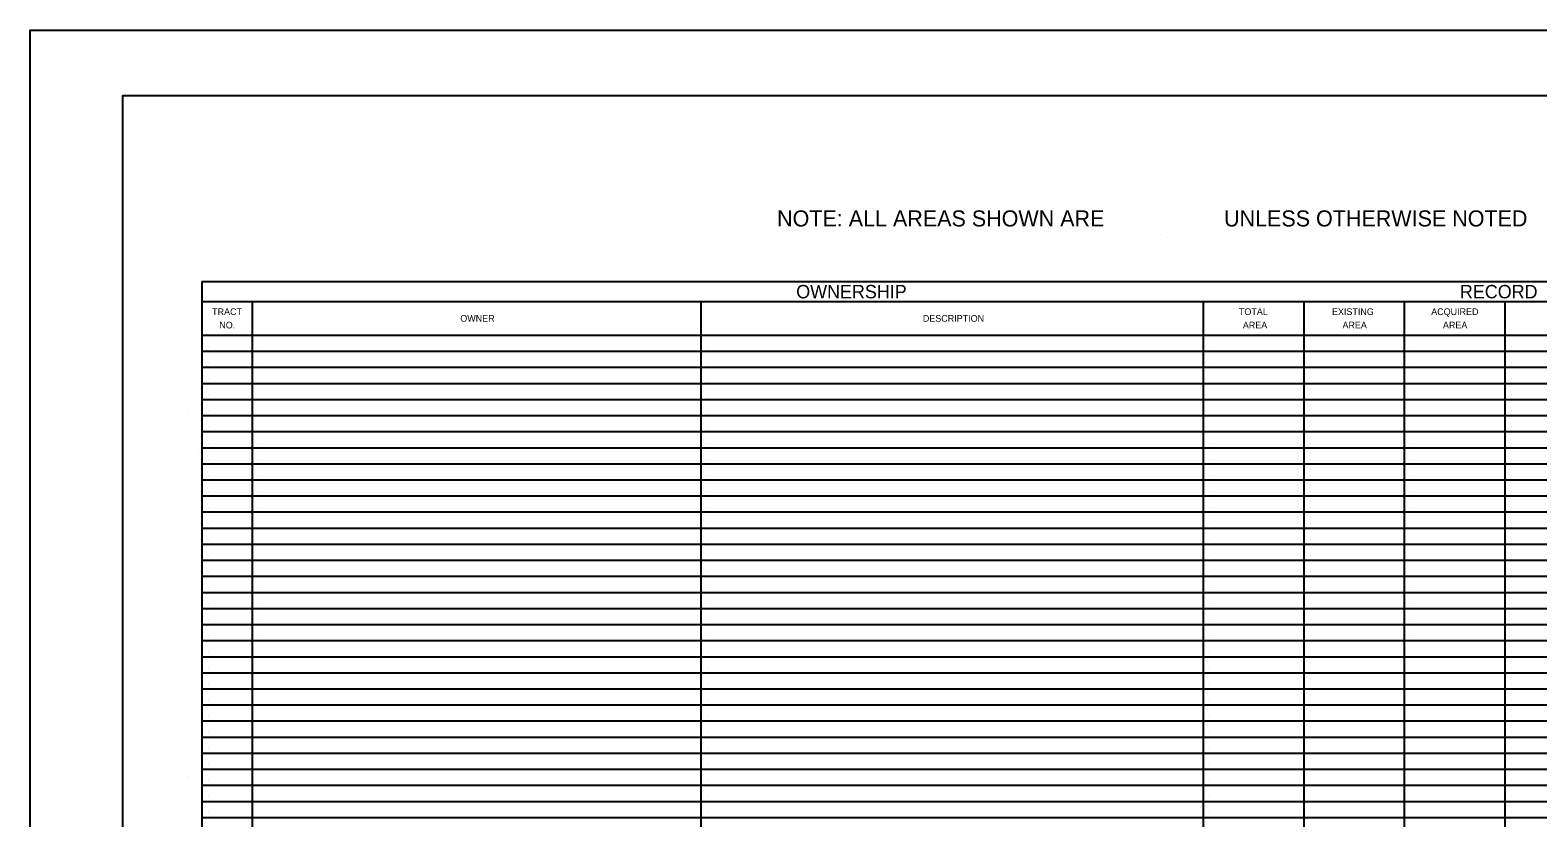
# Model space of a CAD drawing. Extents: x 0 to 3.48, y 0 to 2.25.
# Drawn here: x 0 to 1.913, y 1 to 2 of the extents above; entities that cross this region are included whole.
import ezdxf

# ---------------------------------------------------------------- set-up
doc = ezdxf.new("R2010")
doc.units = 0
for name, color, linetype in [('Border Active Points', 7, 'Continuous'), ('Border Line', 7, 'Continuous'), ('Border Organizer Shape', 7, 'Continuous')]:
    doc.layers.add(name, color=color, linetype=linetype)

msp = doc.modelspace()

# ---------------------------------------------------------------- linework, layer by layer
at = {"layer": 'Border Active Points'}
for p, q in [((1.4437, 1.7373), (1.4437, 1.7373)), ((0.2262, 1.5985), (0.2262, 1.5985)), ((0.29, 1.5985), (0.29, 1.5985)), ((0.8595, 1.5985), (0.8595, 1.5985)), ((1.497, 1.5985), (1.497, 1.5985)), ((1.6245, 1.5985), (1.6245, 1.5985)), ((1.752, 1.5985), (1.752, 1.5985)), ((1.8795, 1.5985), (1.8795, 1.5985)), ((0.2262, 1.5781), (0.2262, 1.5781)), ((0.29, 1.5781), (0.29, 1.5781)), ((0.8595, 1.5781), (0.8595, 1.5781)), ((1.497, 1.5781), (1.497, 1.5781)), ((1.6245, 1.5781), (1.6245, 1.5781)), ((1.752, 1.5781), (1.752, 1.5781)), ((1.8795, 1.5781), (1.8795, 1.5781)), ((0.2262, 1.5577), (0.2262, 1.5577)), ((0.29, 1.5577), (0.29, 1.5577)), ((0.8595, 1.5577), (0.8595, 1.5577)), ((1.497, 1.5577), (1.497, 1.5577)), ((1.6245, 1.5577), (1.6245, 1.5577)), ((1.752, 1.5577), (1.752, 1.5577)), ((1.8795, 1.5577), (1.8795, 1.5577)), ((0.2262, 1.5373), (0.2262, 1.5373)), ((0.29, 1.5373), (0.29, 1.5373)), ((0.8595, 1.5373), (0.8595, 1.5373)), ((1.497, 1.5373), (1.497, 1.5373)), ((1.6245, 1.5373), (1.6245, 1.5373)), ((1.752, 1.5373), (1.752, 1.5373)), ((1.8795, 1.5373), (1.8795, 1.5373)), ((0.2002, 1.5179), (0.2002, 1.5179)), ((0.2262, 1.5169), (0.2262, 1.5169)), ((0.29, 1.5169), (0.29, 1.5169)), ((0.8595, 1.5169), (0.8595, 1.5169)), ((1.497, 1.5169), (1.497, 1.5169)), ((1.6245, 1.5169), (1.6245, 1.5169)), ((1.752, 1.5169), (1.752, 1.5169)), ((1.8795, 1.5169), (1.8795, 1.5169)), ((0.2262, 1.4965), (0.2262, 1.4965)), ((0.29, 1.4965), (0.29, 1.4965)), ((0.8595, 1.4965), (0.8595, 1.4965)), ((1.497, 1.4965), (1.497, 1.4965)), ((1.6245, 1.4965), (1.6245, 1.4965)), ((1.752, 1.4965), (1.752, 1.4965)), ((1.8795, 1.4965), (1.8795, 1.4965)), ((0.2262, 1.4761), (0.2262, 1.4761)), ((0.29, 1.4761), (0.29, 1.4761)), ((0.8595, 1.4761), (0.8595, 1.4761)), ((1.497, 1.4761), (1.497, 1.4761)), ((1.6245, 1.4761), (1.6245, 1.4761)), ((1.752, 1.4761), (1.752, 1.4761)), ((1.8795, 1.4761), (1.8795, 1.4761)), ((0.2142, 1.4665), (0.2142, 1.4665)), ((0.2262, 1.4557), (0.2262, 1.4557)), ((0.29, 1.4557), (0.29, 1.4557)), ((0.8595, 1.4557), (0.8595, 1.4557)), ((1.497, 1.4557), (1.497, 1.4557)), ((1.6245, 1.4557), (1.6245, 1.4557)), ((1.752, 1.4557), (1.752, 1.4557)), ((1.8795, 1.4557), (1.8795, 1.4557)), ((0.2262, 1.4353), (0.2262, 1.4353)), ((0.29, 1.4353), (0.29, 1.4353)), ((0.8595, 1.4353), (0.8595, 1.4353)), ((1.497, 1.4353), (1.497, 1.4353)), ((1.6245, 1.4353), (1.6245, 1.4353)), ((1.752, 1.4353), (1.752, 1.4353)), ((1.8795, 1.4353), (1.8795, 1.4353)), ((0.2262, 1.4149), (0.2262, 1.4149)), ((0.29, 1.4149), (0.29, 1.4149)), ((0.8595, 1.4149), (0.8595, 1.4149)), ((1.497, 1.4149), (1.497, 1.4149)), ((1.6245, 1.4149), (1.6245, 1.4149)), ((1.752, 1.4149), (1.752, 1.4149)), ((1.8795, 1.4149), (1.8795, 1.4149)), ((0.2262, 1.3945), (0.2262, 1.3945)), ((0.29, 1.3945), (0.29, 1.3945)), ((0.8595, 1.3945), (0.8595, 1.3945)), ((1.497, 1.3945), (1.497, 1.3945)), ((1.6245, 1.3945), (1.6245, 1.3945)), ((1.752, 1.3945), (1.752, 1.3945)), ((1.8795, 1.3945), (1.8795, 1.3945)), ((0.2262, 1.3741), (0.2262, 1.3741)), ((0.29, 1.3741), (0.29, 1.3741)), ((0.8595, 1.3741), (0.8595, 1.3741)), ((1.497, 1.3741), (1.497, 1.3741)), ((1.6245, 1.3741), (1.6245, 1.3741)), ((1.752, 1.3741), (1.752, 1.3741)), ((1.8795, 1.3741), (1.8795, 1.3741)), ((0.2262, 1.3537), (0.2262, 1.3537)), ((0.29, 1.3537), (0.29, 1.3537)), ((0.8595, 1.3537), (0.8595, 1.3537)), ((1.497, 1.3537), (1.497, 1.3537)), ((1.6245, 1.3537), (1.6245, 1.3537)), ((1.752, 1.3537), (1.752, 1.3537)), ((1.8795, 1.3537), (1.8795, 1.3537)), ((0.2262, 1.3333), (0.2262, 1.3333)), ((0.29, 1.3333), (0.29, 1.3333)), ((0.8595, 1.3333), (0.8595, 1.3333)), ((1.497, 1.3333), (1.497, 1.3333)), ((1.6245, 1.3333), (1.6245, 1.3333)), ((1.752, 1.3333), (1.752, 1.3333)), ((1.8795, 1.3333), (1.8795, 1.3333)), ((0.2262, 1.3129), (0.2262, 1.3129)), ((0.29, 1.3129), (0.29, 1.3129)), ((0.8595, 1.3129), (0.8595, 1.3129)), ((1.497, 1.3129), (1.497, 1.3129)), ((1.6245, 1.3129), (1.6245, 1.3129)), ((1.752, 1.3129), (1.752, 1.3129)), ((1.8795, 1.3129), (1.8795, 1.3129)), ((0.2262, 1.2925), (0.2262, 1.2925)), ((0.29, 1.2925), (0.29, 1.2925)), ((0.8595, 1.2925), (0.8595, 1.2925)), ((1.497, 1.2925), (1.497, 1.2925)), ((1.6245, 1.2925), (1.6245, 1.2925)), ((1.752, 1.2925), (1.752, 1.2925)), ((1.8795, 1.2925), (1.8795, 1.2925)), ((0.2262, 1.2721), (0.2262, 1.2721)), ((0.29, 1.2721), (0.29, 1.2721)), ((0.8595, 1.2721), (0.8595, 1.2721)), ((1.497, 1.2721), (1.497, 1.2721)), ((1.6245, 1.2721), (1.6245, 1.2721)), ((1.752, 1.2721), (1.752, 1.2721)), ((1.8795, 1.2721), (1.8795, 1.2721)), ((0.2262, 1.2517), (0.2262, 1.2517)), ((0.29, 1.2517), (0.29, 1.2517)), ((0.8595, 1.2517), (0.8595, 1.2517)), ((1.497, 1.2517), (1.497, 1.2517)), ((1.6245, 1.2517), (1.6245, 1.2517)), ((1.752, 1.2517), (1.752, 1.2517)), ((1.8795, 1.2517), (1.8795, 1.2517)), ((0.2262, 1.2313), (0.2262, 1.2313)), ((0.29, 1.2313), (0.29, 1.2313)), ((0.8595, 1.2313), (0.8595, 1.2313)), ((1.497, 1.2313), (1.497, 1.2313)), ((1.6245, 1.2313), (1.6245, 1.2313)), ((1.752, 1.2313), (1.752, 1.2313)), ((1.8795, 1.2313), (1.8795, 1.2313)), ((0.2262, 1.2109), (0.2262, 1.2109)), ((0.29, 1.2109), (0.29, 1.2109)), ((0.8595, 1.2109), (0.8595, 1.2109)), ((1.497, 1.2109), (1.497, 1.2109)), ((1.6245, 1.2109), (1.6245, 1.2109)), ((1.752, 1.2109), (1.752, 1.2109)), ((1.8795, 1.2109), (1.8795, 1.2109)), ((0.2262, 1.1905), (0.2262, 1.1905)), ((0.29, 1.1905), (0.29, 1.1905)), ((0.8595, 1.1905), (0.8595, 1.1905)), ((1.497, 1.1905), (1.497, 1.1905)), ((1.6245, 1.1905), (1.6245, 1.1905)), ((1.752, 1.1905), (1.752, 1.1905)), ((1.8795, 1.1905), (1.8795, 1.1905)), ((0.2262, 1.1701), (0.2262, 1.1701)), ((0.29, 1.1701), (0.29, 1.1701)), ((0.8595, 1.1701), (0.8595, 1.1701)), ((1.497, 1.1701), (1.497, 1.1701)), ((1.6245, 1.1701), (1.6245, 1.1701)), ((1.752, 1.1701), (1.752, 1.1701)), ((1.8795, 1.1701), (1.8795, 1.1701)), ((0.2262, 1.1497), (0.2262, 1.1497)), ((0.29, 1.1497), (0.29, 1.1497)), ((0.8595, 1.1497), (0.8595, 1.1497)), ((1.497, 1.1497), (1.497, 1.1497)), ((1.6245, 1.1497), (1.6245, 1.1497)), ((1.752, 1.1497), (1.752, 1.1497)), ((1.8795, 1.1497), (1.8795, 1.1497)), ((0.2262, 1.1293), (0.2262, 1.1293)), ((0.29, 1.1293), (0.29, 1.1293)), ((0.8595, 1.1293), (0.8595, 1.1293)), ((1.497, 1.1293), (1.497, 1.1293)), ((1.6245, 1.1293), (1.6245, 1.1293)), ((1.752, 1.1293), (1.752, 1.1293)), ((1.8795, 1.1293), (1.8795, 1.1293)), ((0.2262, 1.1089), (0.2262, 1.1089)), ((0.29, 1.1089), (0.29, 1.1089)), ((0.8595, 1.1089), (0.8595, 1.1089)), ((1.497, 1.1089), (1.497, 1.1089)), ((1.6245, 1.1089), (1.6245, 1.1089)), ((1.752, 1.1089), (1.752, 1.1089)), ((1.8795, 1.1089), (1.8795, 1.1089)), ((0.2262, 1.0885), (0.2262, 1.0885)), ((0.29, 1.0885), (0.29, 1.0885)), ((0.8595, 1.0885), (0.8595, 1.0885)), ((1.497, 1.0885), (1.497, 1.0885)), ((1.6245, 1.0885), (1.6245, 1.0885)), ((1.752, 1.0885), (1.752, 1.0885)), ((1.8795, 1.0885), (1.8795, 1.0885)), ((0.2262, 1.0681), (0.2262, 1.0681)), ((0.29, 1.0681), (0.29, 1.0681)), ((0.8595, 1.0681), (0.8595, 1.0681)), ((1.497, 1.0681), (1.497, 1.0681)), ((1.6245, 1.0681), (1.6245, 1.0681)), ((1.752, 1.0681), (1.752, 1.0681)), ((1.8795, 1.0681), (1.8795, 1.0681)), ((0.2002, 1.0514), (0.2002, 1.0514)), ((0.2262, 1.0477), (0.2262, 1.0477)), ((0.29, 1.0477), (0.29, 1.0477)), ((0.8595, 1.0477), (0.8595, 1.0477)), ((1.497, 1.0477), (1.497, 1.0477)), ((1.6245, 1.0477), (1.6245, 1.0477)), ((1.752, 1.0477), (1.752, 1.0477)), ((1.8795, 1.0477), (1.8795, 1.0477)), ((0.2262, 1.0273), (0.2262, 1.0273)), ((0.29, 1.0273), (0.29, 1.0273)), ((0.8595, 1.0273), (0.8595, 1.0273)), ((1.497, 1.0273), (1.497, 1.0273)), ((1.6245, 1.0273), (1.6245, 1.0273)), ((1.752, 1.0273), (1.752, 1.0273)), ((1.8795, 1.0273), (1.8795, 1.0273)), ((0.2262, 1.0069), (0.2262, 1.0069)), ((0.29, 1.0069), (0.29, 1.0069)), ((0.8595, 1.0069), (0.8595, 1.0069)), ((1.497, 1.0069), (1.497, 1.0069)), ((1.6245, 1.0069), (1.6245, 1.0069)), ((1.752, 1.0069), (1.752, 1.0069)), ((1.8795, 1.0069), (1.8795, 1.0069))]:
    msp.add_line(p, q, dxfattribs=at)
at = {"layer": 'Border Line'}
for p, q in [((0.2177, 1.681), (2.6827, 1.681)), ((0.2177, 1.681), (0.2177, 0.185)), ((0.2177, 1.6555), (2.6827, 1.6555)), ((0.2815, 1.6555), (0.2815, 0.185)), ((0.851, 1.6555), (0.851, 0.1893)), ((1.4885, 1.6555), (1.4885, 0.185)), ((1.616, 1.6555), (1.616, 0.185)), ((1.7435, 1.6555), (1.7435, 0.185)), ((1.871, 1.6555), (1.871, 0.185)), ((0.2177, 1.613), (2.6827, 1.613)), ((0.2177, 1.5926), (2.6827, 1.5926)), ((0.2177, 1.5722), (2.6827, 1.5722)), ((0.2177, 1.5518), (2.6827, 1.5518)), ((0.2177, 1.5314), (2.6827, 1.5314)), ((0.2177, 1.511), (2.6827, 1.511)), ((0.2177, 1.4906), (2.6827, 1.4906)), ((0.2177, 1.4702), (2.6827, 1.4702)), ((0.2177, 1.4498), (2.6827, 1.4498)), ((0.2177, 1.4294), (2.6827, 1.4294)), ((0.2177, 1.409), (2.6827, 1.409)), ((0.2177, 1.3886), (2.6827, 1.3886)), ((0.2177, 1.3682), (2.6827, 1.3682)), ((0.2177, 1.3478), (2.6827, 1.3478)), ((0.2177, 1.3274), (2.6827, 1.3274)), ((0.2177, 1.307), (2.6827, 1.307)), ((0.2177, 1.2866), (2.6827, 1.2866)), ((0.2177, 1.2662), (2.6827, 1.2662)), ((0.2177, 1.2458), (2.6827, 1.2458)), ((0.2177, 1.2254), (2.6827, 1.2254)), ((0.2177, 1.205), (2.6827, 1.205)), ((0.2177, 1.1846), (2.6827, 1.1846)), ((0.2177, 1.1642), (2.6827, 1.1642)), ((0.2177, 1.1438), (2.6827, 1.1438)), ((0.2177, 1.1234), (2.6827, 1.1234)), ((0.2177, 1.103), (2.6827, 1.103)), ((0.2177, 1.0826), (2.6827, 1.0826)), ((0.2177, 1.0622), (2.6827, 1.0622)), ((0.2177, 1.0418), (2.6827, 1.0418)), ((0.2177, 1.0214), (2.6827, 1.0214)), ((0.2177, 1.001), (2.6827, 1.001))]:
    msp.add_line(p, q, dxfattribs=at)
msp.add_lwpolyline([(0.117, 0.0835), (2.95, 0.0835), (2.95, 1.9165), (0.117, 1.9165)], close=True, dxfattribs=at)
at = {"layer": 'Border Organizer Shape'}
msp.add_lwpolyline([(3, 0), (0, 0), (0, 2), (3, 2)], close=True, dxfattribs=at)

# ---------------------------------------------------------------- texts
at = {"layer": 'Border Line'}
for s, height, p in [('NOTE: ALL AREAS SHOWN ARE   ', 0.0204, (0.9477, 1.7509)), ('        UNLESS OTHERWISE NOTED', 0.0204, (1.4542, 1.7509)), ('OWNERSHIP', 0.017, (0.972, 1.6597)), ('RECORD', 0.017, (1.8141, 1.6597)), ('TRACT', 0.0085, (0.2309, 1.6385)), ('TOTAL', 0.0085, (1.5337, 1.6385)), ('EXISTING', 0.0085, (1.6518, 1.6385)), ('ACQUIRED', 0.0085, (1.7777, 1.6385)), ('NO.', 0.0085, (0.24, 1.6215)), ('OWNER', 0.0085, (0.5458, 1.63)), ('DESCRIPTION', 0.0085, (1.1327, 1.63)), ('AREA', 0.0085, (1.5387, 1.6215)), ('AREA', 0.0085, (1.6651, 1.6215)), ('AREA', 0.0085, (1.7926, 1.6215))]:
    msp.add_text(s, height=height, dxfattribs=at).set_placement(p)

doc.saveas('drawing.dxf')
